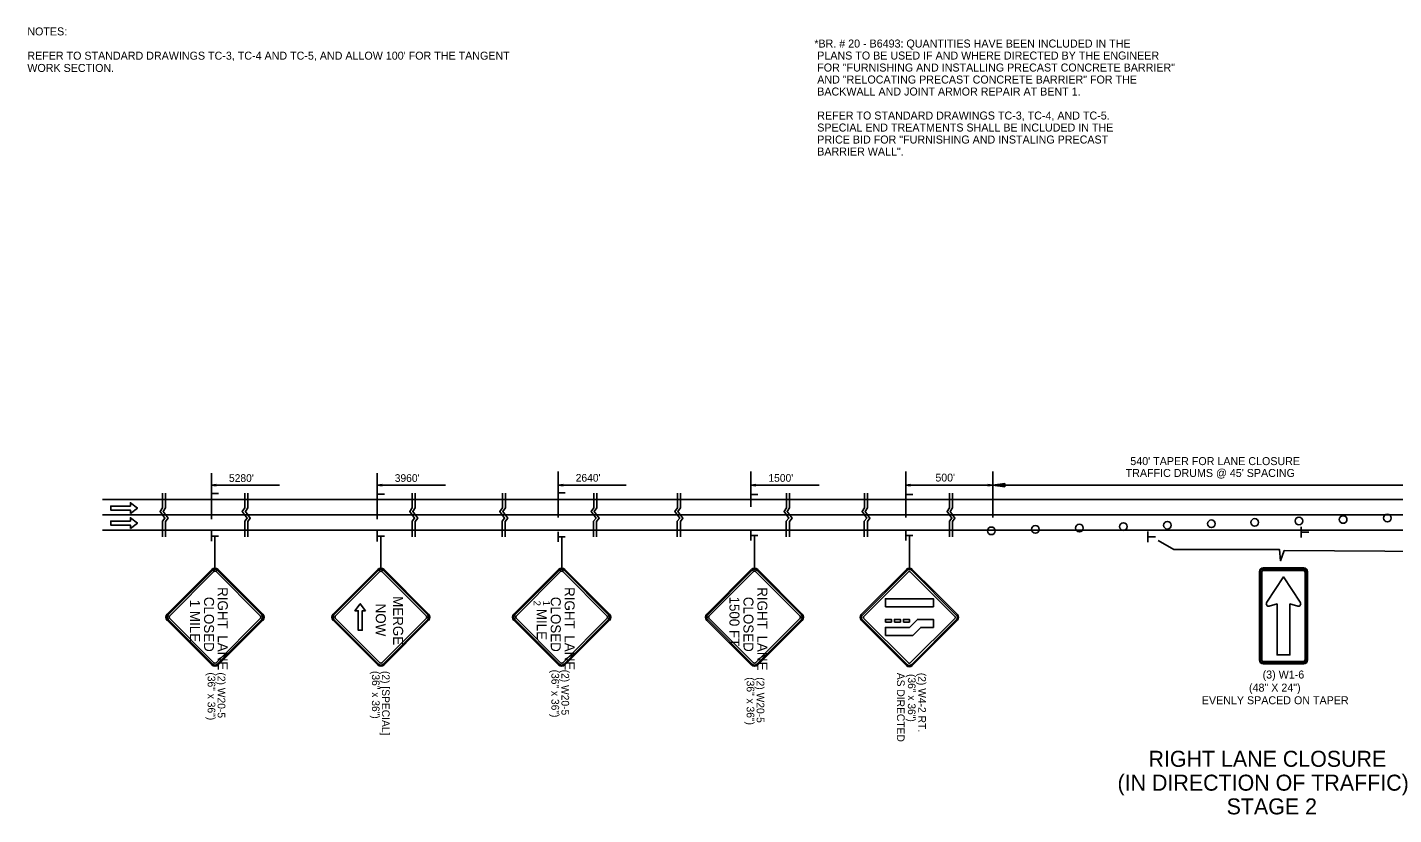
# Model space of a CAD drawing. Extents: x 1930579 to 1938222, y 596452 to 597761.
# Drawn here: x 1936670 to 1937695, y 597170 to 597761 of the extents above; entities that cross this region are included whole.
import ezdxf

# ---------------------------------------------------------------- set-up
doc = ezdxf.new("R2010")
doc.units = 0
for name, color, linetype in [('Default', 7, 'Continuous'), ('P_TC_Signs_Permanent', 7, 'Continuous'), ('P_TC_Signs_Temporary', 7, 'Continuous'), ('R_Border', 7, 'Continuous'), ('R_MOT', 7, 'Continuous'), ('R_Striping', 7, 'Continuous')]:
    doc.layers.add(name, color=color, linetype=linetype)

msp = doc.modelspace()

# ---------------------------------------------------------------- linework, layer by layer
at = {"layer": 'Default'}
for p, q in [((1936808.5, 597426.4), (1936808.5, 597391.9)), ((1936932.9, 597426.4), (1936932.9, 597391.9)), ((1937068.5, 597427.6), (1937068.5, 597393.1)), ((1937213.1, 597427.6), (1937213.1, 597401.3)), ((1937329.2, 597427.6), (1937329.2, 597393.1)), ((1937394.5, 597427.6), (1937394.5, 597393.1)), ((1937394.5, 597417.4), (1937403.4, 597418.8)), ((1937403.4, 597418.8), (1937403.4, 597416.1)), ((1936812.2, 597418), (1936808.5, 597417.4)), ((1936808.5, 597417.4), (1936859.6, 597417.4)), ((1936812.2, 597416.9), (1936808.5, 597417.4)), ((1936808.5, 597414.9), (1936808.5, 597407.3)), ((1936808.6, 597411.1), (1936813.8, 597411.1)), ((1936812.2, 597417.9), (1936809.1, 597417.4)), ((1936812.2, 597417), (1936809.1, 597417.4)), ((1936812.2, 597417.8), (1936809.7, 597417.4)), ((1936812.2, 597417.1), (1936809.7, 597417.4)), ((1936812.2, 597417.7), (1936810.3, 597417.4)), ((1936812.2, 597417.2), (1936810.3, 597417.4)), ((1936812.2, 597417.6), (1936811, 597417.4)), ((1936812.2, 597417.3), (1936811, 597417.4)), ((1936812.2, 597417.5), (1936811.6, 597417.4)), ((1936812.2, 597417.4), (1936811.6, 597417.4)), ((1936812.2, 597416.9), (1936812.2, 597418)), ((1936936.5, 597418), (1936932.9, 597417.4)), ((1936932.9, 597417.4), (1936984, 597417.4)), ((1936936.5, 597416.9), (1936932.9, 597417.4)), ((1936932.9, 597414.4), (1936932.9, 597406.7)), ((1936933, 597410.6), (1936938.2, 597410.6)), ((1936936.5, 597417.9), (1936933.5, 597417.4)), ((1936936.5, 597417), (1936933.5, 597417.4)), ((1936936.5, 597417.8), (1936934.1, 597417.4)), ((1936936.5, 597417.1), (1936934.1, 597417.4)), ((1936936.5, 597417.7), (1936934.7, 597417.4)), ((1936936.5, 597417.2), (1936934.7, 597417.4)), ((1936936.5, 597417.6), (1936935.3, 597417.4)), ((1936936.5, 597417.3), (1936935.3, 597417.4)), ((1936936.5, 597417.5), (1936935.9, 597417.4)), ((1936936.5, 597417.4), (1936935.9, 597417.4)), ((1936936.5, 597416.9), (1936936.5, 597418)), ((1937072.2, 597418), (1937068.5, 597417.4)), ((1937068.5, 597417.4), (1937119.6, 597417.4)), ((1937072.2, 597416.9), (1937068.5, 597417.4)), ((1937068.5, 597415.4), (1937068.5, 597407.7)), ((1937068.6, 597411.6), (1937073.8, 597411.6)), ((1937072.2, 597417.9), (1937069.1, 597417.4)), ((1937072.2, 597417), (1937069.1, 597417.4)), ((1937072.2, 597417.8), (1937069.7, 597417.4)), ((1937072.2, 597417.1), (1937069.7, 597417.4)), ((1937072.2, 597417.7), (1937070.4, 597417.4)), ((1937072.2, 597417.2), (1937070.4, 597417.4)), ((1937072.2, 597417.6), (1937071, 597417.4)), ((1937072.2, 597417.3), (1937071, 597417.4)), ((1937072.2, 597417.5), (1937071.6, 597417.4)), ((1937072.2, 597417.4), (1937071.6, 597417.4)), ((1937072.2, 597416.9), (1937072.2, 597418)), ((1937216.7, 597418), (1937213.1, 597417.4)), ((1937213.1, 597417.4), (1937264.2, 597417.4)), ((1937216.7, 597416.9), (1937213.1, 597417.4)), ((1937213.1, 597414.4), (1937213.1, 597406.7)), ((1937213.2, 597410.5), (1937218.4, 597410.5)), ((1937216.7, 597417.9), (1937213.7, 597417.4)), ((1937216.7, 597417), (1937213.7, 597417.4)), ((1937216.7, 597417.8), (1937214.3, 597417.4)), ((1937216.7, 597417.1), (1937214.3, 597417.4)), ((1937216.7, 597417.7), (1937214.9, 597417.4)), ((1937216.7, 597417.2), (1937214.9, 597417.4)), ((1937216.7, 597417.6), (1937215.5, 597417.4)), ((1937216.7, 597417.3), (1937215.5, 597417.4)), ((1937216.7, 597417.5), (1937216.1, 597417.4)), ((1937216.7, 597417.4), (1937216.1, 597417.4)), ((1937216.7, 597416.9), (1937216.7, 597418)), ((1937332.8, 597418), (1937329.2, 597417.4)), ((1937329.2, 597417.4), (1937394.5, 597417.4)), ((1937332.8, 597416.9), (1937329.2, 597417.4)), ((1937329.2, 597414.3), (1937329.2, 597406.7)), ((1937329.3, 597410.5), (1937334.5, 597410.5)), ((1937332.8, 597417.9), (1937329.8, 597417.4)), ((1937332.8, 597417), (1937329.8, 597417.4)), ((1937332.8, 597417.8), (1937330.4, 597417.4)), ((1937332.8, 597417.1), (1937330.4, 597417.4)), ((1937332.8, 597417.7), (1937331, 597417.4)), ((1937332.8, 597417.2), (1937331, 597417.4)), ((1937332.8, 597417.6), (1937331.7, 597417.4)), ((1937332.8, 597417.3), (1937331.7, 597417.4)), ((1937332.8, 597417.5), (1937332.3, 597417.4)), ((1937332.8, 597417.4), (1937332.3, 597417.4)), ((1937332.8, 597416.9), (1937332.8, 597418)), ((1937390.8, 597418), (1937394.5, 597417.4)), ((1937390.8, 597418), (1937390.8, 597416.9)), ((1937390.8, 597417.9), (1937393.9, 597417.4)), ((1937390.8, 597417.8), (1937393.3, 597417.4)), ((1937390.8, 597417.7), (1937392.7, 597417.4)), ((1937390.8, 597417.6), (1937392, 597417.4)), ((1937390.8, 597417.5), (1937391.4, 597417.4)), ((1937390.8, 597416.9), (1937394.5, 597417.4)), ((1937390.8, 597417.3), (1937392, 597417.4)), ((1937390.8, 597417.1), (1937393.3, 597417.4)), ((1937390.8, 597417), (1937393.9, 597417.4)), ((1937390.8, 597417.2), (1937392.7, 597417.4)), ((1937390.8, 597417.4), (1937391.4, 597417.4)), ((1937761.7, 597417.4), (1937394.5, 597417.4)), ((1937403.4, 597416.1), (1937394.5, 597417.4)), ((1937394.5, 597406.7), (1936726.8, 597406.7)), ((1938013.5, 597406.7), (1937394.5, 597406.7)), ((1938013.5, 597395.1), (1936726.8, 597395.1)), ((1937394.5, 597383.6), (1936726.8, 597383.6)), ((1936808.5, 597375.4), (1936808.5, 597383)), ((1936808.6, 597379.2), (1936813.8, 597379.2)), ((1936892.9, 597383.6), (1936960.5, 597383.6)), ((1936932.9, 597375.3), (1936932.9, 597383)), ((1936933, 597379.1), (1936938.2, 597379.1)), ((1937068.5, 597374.9), (1937068.5, 597382.5)), ((1937068.6, 597378.7), (1937073.8, 597378.7)), ((1937213.1, 597375.9), (1937213.1, 597383.6)), ((1937213.2, 597379.8), (1937218.4, 597379.8)), ((1937329.2, 597376), (1937329.2, 597383.6)), ((1937329.3, 597379.8), (1937334.5, 597379.8)), ((1938013.5, 597383.6), (1937394.5, 597383.6)), ((1937510.8, 597374.7), (1937510.8, 597382.7)), ((1937510.9, 597378.7), (1937516.4, 597378.7)), ((1937625.8, 597378.2), (1937625.8, 597386.2)), ((1937625.9, 597382.1), (1937631.4, 597382.1))]:
    msp.add_line(p, q, dxfattribs=at)
for points in [[(1936771.9, 597411.5), (1936771.9, 597400.5), (1936770.1, 597397.7), (1936773.7, 597392.7), (1936771.8, 597390.4), (1936771.8, 597378.8)], [(1936774.2, 597411.5), (1936774.2, 597400.4), (1936772.4, 597397.6), (1936776, 597392.6), (1936774.1, 597390.3), (1936774.1, 597378.8)], [(1936833.6, 597411.5), (1936833.6, 597400.5), (1936831.7, 597397.7), (1936835.4, 597392.7), (1936833.5, 597390.4), (1936833.5, 597378.8)], [(1936835.9, 597411.5), (1936835.9, 597400.4), (1936834, 597397.6), (1936837.7, 597392.6), (1936835.8, 597390.3), (1936835.8, 597378.8)], [(1936959.1, 597411.5), (1936959.1, 597400.5), (1936957.2, 597397.7), (1936960.9, 597392.7), (1936959, 597390.4), (1936959, 597378.8)], [(1936961.4, 597411.5), (1936961.4, 597400.4), (1936959.5, 597397.6), (1936963.2, 597392.6), (1936961.3, 597390.3), (1936961.3, 597378.8)], [(1937026.7, 597411.5), (1937026.7, 597400.5), (1937024.8, 597397.7), (1937028.4, 597392.7), (1937026.5, 597390.4), (1937026.5, 597378.8)], [(1937029, 597411.5), (1937029, 597400.4), (1937027.1, 597397.6), (1937030.7, 597392.6), (1937028.8, 597390.3), (1937028.8, 597378.8)], [(1937095.2, 597411.5), (1937095.2, 597400.5), (1937093.3, 597397.7), (1937097, 597392.7), (1937095, 597390.4), (1937095, 597378.8)], [(1937097.5, 597411.5), (1937097.5, 597400.4), (1937095.6, 597397.6), (1937099.3, 597392.6), (1937097.3, 597390.3), (1937097.3, 597378.8)], [(1937158, 597411.5), (1937158, 597400.5), (1937156.1, 597397.7), (1937159.8, 597392.7), (1937157.9, 597390.4), (1937157.9, 597378.8)], [(1937160.3, 597411.5), (1937160.3, 597400.4), (1937158.4, 597397.6), (1937162.1, 597392.6), (1937160.2, 597390.3), (1937160.2, 597378.8)], [(1937239.8, 597411.5), (1937239.8, 597400.5), (1937237.9, 597397.7), (1937241.6, 597392.7), (1937239.6, 597390.4), (1937239.6, 597378.8)], [(1937242.1, 597411.5), (1937242.1, 597400.4), (1937240.2, 597397.6), (1937243.9, 597392.6), (1937241.9, 597390.3), (1937241.9, 597378.8)], [(1937298.2, 597411.5), (1937298.2, 597400.5), (1937296.4, 597397.7), (1937300, 597392.7), (1937298.1, 597390.4), (1937298.1, 597378.8)], [(1937300.5, 597411.5), (1937300.5, 597400.4), (1937298.7, 597397.6), (1937302.3, 597392.6), (1937300.4, 597390.3), (1937300.4, 597378.8)], [(1937362, 597411.5), (1937362, 597400.5), (1937360.2, 597397.7), (1937363.8, 597392.7), (1937361.9, 597390.4), (1937361.9, 597378.8)], [(1937364.3, 597411.5), (1937364.3, 597400.4), (1937362.5, 597397.6), (1937366.1, 597392.6), (1937364.2, 597390.3), (1937364.2, 597378.8)]]:
    msp.add_lwpolyline(points, dxfattribs=at)
for centre in [(1937459.4, 597385.3), (1937492.4, 597386.4), (1937525.4, 597387.4), (1937558.4, 597388.5), (1937590.9, 597389.5), (1937624, 597390.6), (1937657.2, 597391.7), (1937690.4, 597392.8), (1937393.4, 597383.2), (1937426.4, 597384.3)]:
    msp.add_circle(centre, 2.87, dxfattribs=at)
at = {"layer": 'P_TC_Signs_Permanent'}
for p, q in [((1937295.8, 597320.4), (1937329.8, 597354.3)), ((1937594.4, 597352.5), (1937594.4, 597286.2)), ((1937595.2, 597352.5), (1937595.2, 597286.2)), ((1937596.3, 597352.5), (1937596.3, 597286.2)), ((1937627.6, 597355.4), (1937597.2, 597355.4)), ((1937627.6, 597354.6), (1937597.2, 597354.6)), ((1937627.6, 597353.5), (1937597.2, 597353.5)), ((1937628.6, 597286.2), (1937628.6, 597352.5)), ((1937629.7, 597286.2), (1937629.7, 597352.5)), ((1937630.4, 597286.2), (1937630.4, 597352.5)), ((1937349.9, 597326.3), (1937349.9, 597332.3)), ((1937329.8, 597282.2), (1937295.8, 597316.1)), ((1937368, 597316.1), (1937334, 597282.2)), ((1937597.2, 597285.2), (1937627.6, 597285.2)), ((1937597.2, 597284.1), (1937627.6, 597284.1)), ((1937597.2, 597283.4), (1937627.6, 597283.4))]:
    msp.add_line(p, q, dxfattribs=at)
for points in [[(1937330.4, 597353.7), (1937296.5, 597319.7)], [(1937297.5, 597318.7), (1937331.5, 597352.6)], [(1937332.3, 597352.6), (1937366.3, 597318.7)], [(1937367.3, 597319.7), (1937333.4, 597353.7)], [(1937334, 597354.3), (1937351, 597337.4), (1937368, 597320.4)], [(1937624.9, 597329.6), (1937612.4, 597348.6), (1937600, 597329.6)], [(1937601.8, 597326.7), (1937607.6, 597328.4), (1937607.6, 597290.1), (1937617.3, 597290.1), (1937617.3, 597328.4), (1937623.1, 597326.6)], [(1937296.5, 597316.8), (1937330.4, 597282.8)], [(1937331.5, 597283.9), (1937297.5, 597317.8)], [(1937366.3, 597317.8), (1937332.3, 597283.9)], [(1937333.4, 597282.8), (1937367.3, 597316.8)]]:
    msp.add_lwpolyline(points, dxfattribs=at)
for points in [[(1937313.9, 597326.3), (1937313.9, 597332.3), (1937349.9, 597332.3), (1937349.9, 597326.3)], [(1937313.9, 597314.7), (1937313.9, 597316.8), (1937318.4, 597316.8), (1937318.4, 597314.7)], [(1937313.9, 597304.8), (1937313.9, 597310.8), (1937331.9, 597310.8), (1937337.9, 597316.8), (1937349.9, 597316.8), (1937349.9, 597310.8), (1937340.4, 597310.8), (1937334.4, 597304.8)], [(1937320.7, 597314.7), (1937320.7, 597316.8), (1937325.2, 597316.8), (1937325.2, 597314.7)], [(1937327.4, 597314.7), (1937327.4, 597316.8), (1937331.9, 597316.8), (1937331.9, 597314.7)]]:
    msp.add_lwpolyline(points, close=True, dxfattribs=at)
for centre, radius, start, end in [((1937331.9, 597352.2), 3, 45, 135), ((1937331.9, 597352.2), 2.1, 45, 135), ((1937331.9, 597352.2), 0.6, 45, 135), ((1937597.2, 597352.5), 2.81, 90, 180), ((1937597.2, 597352.5), 2.06, 90, 180), ((1937597.2, 597352.5), 0.938, 90, 180), ((1937627.6, 597352.5), 2.81, 360, 90), ((1937627.6, 597352.5), 2.06, 360, 90), ((1937627.6, 597352.5), 0.938, 360, 90), ((1937601.3, 597328.4), 1.76, 146.5994, 285.9691), ((1937537.2, 597370.6), 75, 326.5994, 326.857), ((1937623.6, 597328.4), 1.8, 254.0309, 33.4755), ((1937687.6, 597370.7), 75, 213.2286, 213.4755), ((1937298, 597318.3), 3, 135, 225), ((1937298, 597318.3), 2.1, 135, 225), ((1937298, 597318.3), 0.6, 135, 225), ((1937365.8, 597318.3), 0.6, 315, 45), ((1937365.8, 597318.3), 2.1, 315, 45), ((1937365.8, 597318.3), 3, 315, 45), ((1937597.2, 597286.2), 2.81, 180, 270), ((1937597.2, 597286.2), 2.06, 180, 270), ((1937597.2, 597286.2), 0.937, 180, 270), ((1937627.6, 597286.2), 2.81, 270, 360), ((1937627.6, 597286.2), 2.06, 270, 360), ((1937627.6, 597286.2), 0.938, 270, 360), ((1937331.9, 597284.3), 3, 225, 315), ((1937331.9, 597284.3), 2.1, 225, 315), ((1937331.9, 597284.3), 0.6, 225, 315)]:
    msp.add_arc(centre, radius, start, end, dxfattribs=at)
at = {"layer": 'P_TC_Signs_Temporary'}
for p, q in [((1936775.4, 597320.8), (1936808.8, 597354.2)), ((1936776.1, 597320.2), (1936809.5, 597353.6)), ((1936777, 597319.2), (1936810.4, 597352.6)), ((1936812, 597352.6), (1936845.4, 597319.2)), ((1936812.9, 597353.6), (1936846.3, 597320.2)), ((1936813.6, 597354.2), (1936847, 597320.8)), ((1936899.8, 597320.8), (1936933.2, 597354.2)), ((1936900.4, 597320.2), (1936933.9, 597353.6)), ((1936901.4, 597319.2), (1936934.8, 597352.6)), ((1936936.4, 597352.6), (1936969.8, 597319.2)), ((1936937.3, 597353.6), (1936970.7, 597320.2)), ((1936938, 597354.2), (1936971.4, 597320.8)), ((1937035.4, 597320.8), (1937068.8, 597354.2)), ((1937036.1, 597320.2), (1937069.5, 597353.6)), ((1937037, 597319.2), (1937070.4, 597352.6)), ((1937072, 597352.6), (1937105.4, 597319.2)), ((1937073, 597353.6), (1937106.4, 597320.2)), ((1937073.6, 597354.2), (1937107, 597320.8)), ((1937180, 597320.8), (1937213.4, 597354.2)), ((1937180.7, 597320.1), (1937214.1, 597353.6)), ((1937181.6, 597319.2), (1937215, 597352.6)), ((1937216.6, 597352.6), (1937250, 597319.2)), ((1937217.5, 597353.6), (1937250.9, 597320.1)), ((1937218.2, 597354.2), (1937251.6, 597320.8)), ((1936808.8, 597282.6), (1936775.4, 597316.1)), ((1936809.5, 597283.3), (1936776.1, 597316.7)), ((1936810.4, 597284.2), (1936777, 597317.6)), ((1936845.4, 597317.6), (1936812, 597284.2)), ((1936846.3, 597316.7), (1936812.9, 597283.3)), ((1936847, 597316.1), (1936813.6, 597282.6)), ((1936933.2, 597282.6), (1936899.8, 597316.1)), ((1936933.9, 597283.3), (1936900.4, 597316.7)), ((1936934.8, 597284.2), (1936901.4, 597317.6)), ((1936969.8, 597317.6), (1936936.4, 597284.2)), ((1936970.7, 597316.7), (1936937.3, 597283.3)), ((1936971.4, 597316.1), (1936938, 597282.6)), ((1937068.8, 597282.6), (1937035.4, 597316.1)), ((1937069.5, 597283.3), (1937036.1, 597316.7)), ((1937070.4, 597284.2), (1937037, 597317.6)), ((1937105.4, 597317.6), (1937072, 597284.2)), ((1937106.4, 597316.7), (1937073, 597283.3)), ((1937107, 597316.1), (1937073.6, 597282.6)), ((1937213.4, 597282.6), (1937180, 597316)), ((1937214.1, 597283.3), (1937180.7, 597316.7)), ((1937215, 597284.2), (1937181.6, 597317.6)), ((1937250, 597317.6), (1937216.6, 597284.2)), ((1937250.9, 597316.7), (1937217.5, 597283.3)), ((1937251.6, 597316), (1937218.2, 597282.6))]:
    msp.add_line(p, q, dxfattribs=at)
for centre, radius, start, end in [((1936811.2, 597351.8), 3.37, 45, 135), ((1936811.2, 597351.8), 2.44, 45, 135), ((1936811.2, 597351.8), 1.12, 45, 135), ((1936935.6, 597351.8), 3.37, 45, 135), ((1936935.6, 597351.8), 2.44, 45, 135), ((1936935.6, 597351.8), 1.12, 45, 135), ((1937071.2, 597351.8), 3.37, 45, 135), ((1937071.2, 597351.8), 2.44, 45, 135), ((1937071.2, 597351.8), 1.12, 45, 135), ((1937215.8, 597351.8), 3.37, 45, 135), ((1937215.8, 597351.8), 2.44, 45, 135), ((1937215.8, 597351.8), 1.12, 45, 135), ((1936777.8, 597318.4), 3.37, 135, 225), ((1936777.8, 597318.4), 2.44, 135, 225), ((1936777.8, 597318.4), 1.13, 135, 225), ((1936844.6, 597318.4), 1.13, 315, 45), ((1936844.6, 597318.4), 2.44, 315, 45), ((1936844.6, 597318.4), 3.38, 315, 45), ((1936902.2, 597318.4), 3.37, 135, 225), ((1936902.2, 597318.4), 2.44, 135, 225), ((1936902.2, 597318.4), 1.13, 135, 225), ((1936969, 597318.4), 1.13, 315, 45), ((1936969, 597318.4), 2.44, 315, 45), ((1936969, 597318.4), 3.38, 315, 45), ((1937037.8, 597318.4), 3.37, 135, 225), ((1937037.8, 597318.4), 2.44, 135, 225), ((1937037.8, 597318.4), 1.13, 135, 225), ((1937104.6, 597318.4), 1.13, 315, 45), ((1937104.6, 597318.4), 2.44, 315, 45), ((1937104.6, 597318.4), 3.37, 315, 45), ((1937182.4, 597318.4), 3.37, 135, 225), ((1937182.4, 597318.4), 2.44, 135, 225), ((1937182.4, 597318.4), 1.13, 135, 225), ((1937249.2, 597318.4), 1.13, 315, 45), ((1937249.2, 597318.4), 2.44, 315, 45), ((1937249.2, 597318.4), 3.37, 315, 45), ((1936811.2, 597285), 3.38, 225, 315), ((1936811.2, 597285), 2.44, 225, 315), ((1936811.2, 597285), 1.12, 225, 315), ((1936935.6, 597285), 3.38, 225, 315), ((1936935.6, 597285), 2.44, 225, 315), ((1936935.6, 597285), 1.12, 225, 315), ((1937071.2, 597285), 3.37, 225, 315), ((1937071.2, 597285), 2.44, 225, 315), ((1937071.2, 597285), 1.12, 225, 315), ((1937215.8, 597285), 3.37, 225, 315), ((1937215.8, 597285), 2.44, 225, 315), ((1937215.8, 597285), 1.12, 225, 315)]:
    msp.add_arc(centre, radius, start, end, dxfattribs=at)
at = {"layer": 'R_Border'}
for p, q in [((1936811.2, 597379.2), (1936811.2, 597355.2)), ((1936935.6, 597379.1), (1936935.6, 597355.2)), ((1937071.2, 597378.7), (1937071.2, 597355.2)), ((1937215.8, 597379.8), (1937215.8, 597355.2)), ((1937331.9, 597379.8), (1937331.9, 597355.2))]:
    msp.add_line(p, q, dxfattribs=at)
msp.add_lwpolyline([(1937518.5, 597376), (1937530.3, 597369.1), (1937609.5, 597369.1), (1937610.2, 597360.7), (1937613, 597368.4), (1937726.2, 597367.7), (1937739.4, 597379.5)], dxfattribs=at)
at = {"layer": 'R_MOT'}
msp.add_lwpolyline([(1936924.1, 597323.3), (1936920.1, 597328.5), (1936916.1, 597323.3), (1936918.6, 597323.3), (1936918.6, 597308.6), (1936921.6, 597308.6), (1936921.6, 597323.3)], close=True, dxfattribs=at)
at = {"layer": 'R_Striping'}
for points in [[(1936747.8, 597396.3), (1936753, 597400.3), (1936747.8, 597404.3), (1936747.8, 597401.8), (1936733.1, 597401.8), (1936733.1, 597398.8), (1936747.8, 597398.8)], [(1936747.8, 597385), (1936753, 597389), (1936747.8, 597393), (1936747.8, 597390.5), (1936733.1, 597390.5), (1936733.1, 597387.5), (1936747.8, 597387.5)]]:
    msp.add_lwpolyline(points, close=True, dxfattribs=at)

# ---------------------------------------------------------------- texts
at = {"layer": 'Default'}
for s, height, p in [("TRAFFIC DRUMS @ 45' SPACING ", 6, (1937494.1, 597423.6)), ("540' TAPER FOR LANE CLOSURE", 6, (1937497.6, 597432.5)), ("5280'", 5.76, (1936821.7, 597419.9)), ("3960'", 5.76, (1936946, 597419.9)), ("2640'", 5.76, (1937081.7, 597420.1)), ("1500'", 5.76, (1937226.2, 597420)), ("500'", 5.88, (1937351.5, 597420.2)), ('RIGHT LANE CLOSURE ', 12, (1937511.2, 597206.2)), ('(IN DIRECTION OF TRAFFIC)', 12, (1937488, 597188.3)), ('STAGE 2', 12, (1937569.8, 597170.5))]:
    msp.add_text(s, height=height, rotation=360, dxfattribs=at).set_placement(p)
at = {"layer": 'P_TC_Signs_Temporary'}
for s, height, p in [('RIGHT\u2002LANE', 7.5, (1936813.3, 597341)), ('RIGHT\u2002LANE', 7.5, (1937073.4, 597341)), ('RIGHT\u2002LANE', 7.5, (1937217.9, 597340.9)), ('1 MILE', 7.5, (1936792.5, 597331.5)), ('CLOSED', 7.5, (1936803, 597333.7)), ('NOW', 7.5, (1936931.8, 597328.6)), ('MERGE', 7.5, (1936944.8, 597334.2)), ('2', 5.25, (1937050.1, 597330.8)), ('1', 5.25, (1937057.1, 597330.8)), ('CLOSED', 7.5, (1937063, 597333.7)), ('1500 FT', 7.5, (1937197, 597333.9)), ('CLOSED', 7.5, (1937207.5, 597333.7)), (' MILE', 7.5, (1937052.5, 597327.5))]:
    msp.add_text(s, height=height, rotation=270, dxfattribs=at).set_placement(p)
at = {"layer": 'R_Border'}
for s, height, rotation, p in [('NOTES:', 6, 360, (1936670.5, 597754.8)), ('*BR. # 20 - B6493: QUANTITIES HAVE BEEN INCLUDED IN THE', 6, 360, (1937260.6, 597745.7)), ("REFER TO STANDARD DRAWINGS TC-3, TC-4 AND TC-5, AND ALLOW 100' FOR THE TANGENT", 6, 360, (1936670.5, 597736.6)), (' PLANS TO BE USED IF AND WHERE DIRECTED BY THE ENGINEER', 6, 360, (1937260.6, 597736.7)), ('WORK SECTION.', 6, 360, (1936670.5, 597727.4)), (' FOR "FURNISHING AND INSTALLING PRECAST CONCRETE BARRIER"', 6, 360, (1937260.6, 597727.7)), (' AND "RELOCATING PRECAST CONCRETE BARRIER" FOR THE', 6, 360, (1937260.6, 597718.7)), (' BACKWALL AND JOINT ARMOR REPAIR AT BENT 1.', 6, 360, (1937260.6, 597709.7)), (' REFER TO STANDARD DRAWINGS TC-3, TC-4, AND TC-5.', 6, 360, (1937260.6, 597691.7)), (' SPECIAL END TREATMENTS SHALL BE INCLUDED IN THE', 6, 360, (1937260.6, 597682.7)), (' PRICE BID FOR "FURNISHING AND INSTALING PRECAST', 6, 360, (1937260.6, 597673.7)), (' BARRIER WALL".', 6, 360, (1937260.6, 597664.7)), ('(36" x 36")', 5.76, 270, (1936805.7, 597277)), ('(2) W20-5', 5.76, 270, (1936813.2, 597277)), ('(36" x 36")', 5.76, 270, (1936928.9, 597278.1)), ('(2) [SPECIAL]', 5.76, 270, (1936936.4, 597278.1)), ('(36" x 36")', 5.76, 270, (1937063.5, 597279.1)), ('(2) W20-5', 5.76, 270, (1937071, 597279.1)), ('AS DIRECTED ', 5.76, 270, (1937322.6, 597276.7)), ('(36" x 36")', 5.76, 270, (1937330.8, 597275.8)), ('(2) W4-2 RT.', 5.76, 270, (1937338.6, 597276.7)), ('(3) W1-6', 6, 0.0075, (1937596.8, 597272.4)), ('(36" x 36")', 5.76, 270, (1937209.9, 597273.4)), ('(2) W20-5', 5.76, 270, (1937217.4, 597273.4)), ('(48" X 24")', 6, 0.0075, (1937586.6, 597262.6)), ('EVENLY SPACED ON TAPER', 6, 0.0075, (1937551.2, 597253.1))]:
    msp.add_text(s, height=height, rotation=rotation, dxfattribs=at).set_placement(p)

doc.saveas('drawing.dxf')
